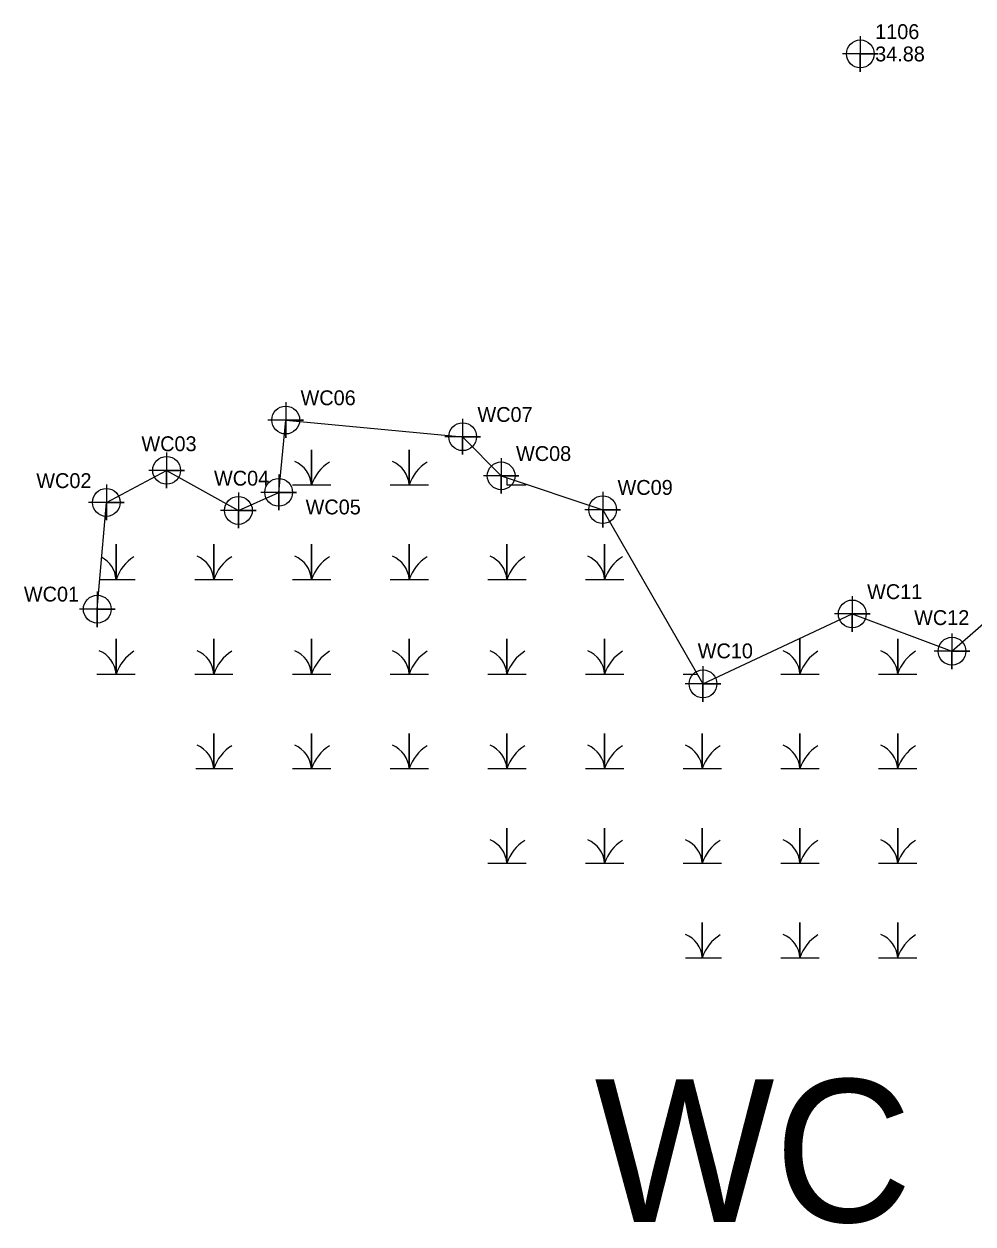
# Model space of a CAD drawing. Extents: x 2138832 to 2141061, y 149156 to 150675.
# Drawn here: x 2140241 to 2140400.8, y 149325.9 to 149527.9 of the extents above; entities that cross this region are included whole.
import ezdxf

# ---------------------------------------------------------------- set-up
doc = ezdxf.new("R2010")
doc.units = 0
for name, color, linetype in [('Default', 7, 'Continuous'), ('Exist Environmental Wetland Boundary', 7, 'Continuous'), ('Exist Environmental Wetland Boundary Cogo Number', 7, 'Continuous'), ('Exist Environmental Wetland Boundary Cogo Point CELL', 7, 'Continuous'), ('Exist Roads EOP Cogo Elevation', 7, 'Continuous'), ('Exist Roads EOP Cogo Number', 7, 'Continuous'), ('Exist Roads EOP Cogo Point CELL', 7, 'Continuous')]:
    doc.layers.add(name, color=color, linetype=linetype)

msp = doc.modelspace()

# ---------------------------------------------------------------- linework, layer by layer
at = {"layer": 'Exist Environmental Wetland Boundary'}
msp.add_lwpolyline([(2140253.29, 149429.4), (2140254.83, 149447.37), (2140264.97, 149452.77), (2140277.06, 149446.02), (2140283.85, 149449.07), (2140285.03, 149461.24), (2140314.82, 149458.43), (2140321.31, 149451.85), (2140338.41, 149446.15), (2140355.29, 149416.83), (2140380.43, 149428.6), (2140397.22, 149422.33), (2140417.64, 149440.18), (2140431.93, 149435.34), (2140440.91, 149448.03), (2140451.84, 149442.55), (2140443.59, 149426.19), (2140443.38, 149418.79), (2140459.22, 149412.06), (2140485.31, 149411.82), (2140462.13, 149440.8)], dxfattribs=at)
at = {"layer": 'Exist Environmental Wetland Boundary Cogo Point CELL'}
msp.add_line((2140351.96, 149418.48), (2140354.34, 149418.48), dxfattribs=at)
for points in [[(2140285.03, 149464.24), (2140285.03, 149458.24), (2140285.03, 149461.24), (2140288.03, 149461.24), (2140282.03, 149461.24)], [(2140314.82, 149461.43), (2140314.82, 149455.43), (2140314.82, 149458.43), (2140317.82, 149458.43), (2140311.82, 149458.43)], [(2140264.97, 149455.77), (2140264.97, 149449.77), (2140264.97, 149452.77), (2140267.97, 149452.77), (2140261.97, 149452.77)], [(2140286.15, 149450.32), (2140289.38, 149450.32), (2140289.38, 149456.24), (2140289.38, 149450.32), (2140292.6, 149450.32)], [(2140302.6, 149450.32), (2140305.83, 149450.32), (2140305.83, 149456.24), (2140305.83, 149450.32), (2140309.05, 149450.32)], [(2140321.31, 149454.85), (2140321.31, 149448.85), (2140321.31, 149451.85), (2140324.31, 149451.85), (2140318.31, 149451.85)], [(2140283.85, 149452.07), (2140283.85, 149446.07), (2140283.85, 149449.07), (2140286.85, 149449.07), (2140280.85, 149449.07)], [(2140254.83, 149450.37), (2140254.83, 149444.37), (2140254.83, 149447.37), (2140257.83, 149447.37), (2140251.83, 149447.37)], [(2140322.28, 149451.53), (2140322.28, 149450.32), (2140325.5, 149450.32)], [(2140277.06, 149449.02), (2140277.06, 149443.02), (2140277.06, 149446.02), (2140280.06, 149446.02), (2140274.06, 149446.02)], [(2140338.41, 149449.15), (2140338.41, 149443.15), (2140338.41, 149446.15), (2140341.41, 149446.15), (2140335.41, 149446.15)], [(2140253.72, 149434.4), (2140256.47, 149434.4), (2140256.47, 149440.32), (2140256.47, 149434.4), (2140259.7, 149434.4)], [(2140269.7, 149434.4), (2140272.93, 149434.4), (2140272.93, 149440.32), (2140272.93, 149434.4), (2140276.15, 149434.4)], [(2140286.15, 149434.4), (2140289.38, 149434.4), (2140289.38, 149440.32), (2140289.38, 149434.4), (2140292.6, 149434.4)], [(2140302.6, 149434.4), (2140305.83, 149434.4), (2140305.83, 149440.32), (2140305.83, 149434.4), (2140309.05, 149434.4)], [(2140319.05, 149434.4), (2140322.28, 149434.4), (2140322.28, 149440.32), (2140322.28, 149434.4), (2140325.5, 149434.4)], [(2140335.5, 149434.4), (2140338.73, 149434.4), (2140338.73, 149440.32), (2140338.73, 149434.4), (2140341.96, 149434.4)], [(2140253.29, 149432.4), (2140253.29, 149426.4), (2140253.29, 149429.4), (2140256.29, 149429.4), (2140250.29, 149429.4)], [(2140380.43, 149431.6), (2140380.43, 149425.6), (2140380.43, 149428.6), (2140383.43, 149428.6), (2140377.43, 149428.6)], [(2140253.25, 149418.48), (2140256.47, 149418.48), (2140256.47, 149424.4), (2140256.47, 149418.48), (2140259.7, 149418.48)], [(2140269.7, 149418.48), (2140272.93, 149418.48), (2140272.93, 149424.4), (2140272.93, 149418.48), (2140276.15, 149418.48)], [(2140286.15, 149418.48), (2140289.38, 149418.48), (2140289.38, 149424.4), (2140289.38, 149418.48), (2140292.6, 149418.48)], [(2140302.6, 149418.48), (2140305.83, 149418.48), (2140305.83, 149424.4), (2140305.83, 149418.48), (2140309.05, 149418.48)], [(2140319.05, 149418.48), (2140322.28, 149418.48), (2140322.28, 149424.4), (2140322.28, 149418.48), (2140325.5, 149418.48)], [(2140335.5, 149418.48), (2140338.73, 149418.48), (2140338.73, 149424.4), (2140338.73, 149418.48), (2140341.96, 149418.48)], [(2140368.41, 149418.48), (2140371.63, 149418.48), (2140371.63, 149424.4), (2140371.63, 149418.48), (2140374.86, 149418.48)], [(2140384.86, 149418.48), (2140388.08, 149418.48), (2140388.08, 149424.4), (2140388.08, 149418.48), (2140391.31, 149418.48)], [(2140397.22, 149425.33), (2140397.22, 149419.33), (2140397.22, 149422.33), (2140400.22, 149422.33), (2140394.22, 149422.33)], [(2140355.29, 149419.83), (2140355.29, 149413.83), (2140355.29, 149416.83), (2140358.29, 149416.83), (2140352.29, 149416.83)], [(2140269.91, 149402.56), (2140272.93, 149402.56), (2140272.93, 149408.48), (2140272.93, 149402.56), (2140276.15, 149402.56)], [(2140286.15, 149402.56), (2140289.38, 149402.56), (2140289.38, 149408.48), (2140289.38, 149402.56), (2140292.6, 149402.56)], [(2140302.6, 149402.56), (2140305.83, 149402.56), (2140305.83, 149408.48), (2140305.83, 149402.56), (2140309.05, 149402.56)], [(2140319.05, 149402.56), (2140322.28, 149402.56), (2140322.28, 149408.48), (2140322.28, 149402.56), (2140325.5, 149402.56)], [(2140335.5, 149402.56), (2140338.73, 149402.56), (2140338.73, 149408.48), (2140338.73, 149402.56), (2140341.96, 149402.56)], [(2140351.96, 149402.56), (2140355.18, 149402.56), (2140355.18, 149408.48), (2140355.18, 149402.56), (2140358.41, 149402.56)], [(2140368.41, 149402.56), (2140371.63, 149402.56), (2140371.63, 149408.48), (2140371.63, 149402.56), (2140374.86, 149402.56)], [(2140384.86, 149402.56), (2140388.08, 149402.56), (2140388.08, 149408.48), (2140388.08, 149402.56), (2140391.31, 149402.56)], [(2140319.05, 149386.65), (2140322.28, 149386.65), (2140322.28, 149392.56), (2140322.28, 149386.65), (2140325.5, 149386.65)], [(2140335.5, 149386.65), (2140338.73, 149386.65), (2140338.73, 149392.56), (2140338.73, 149386.65), (2140341.96, 149386.65)], [(2140351.96, 149386.65), (2140355.18, 149386.65), (2140355.18, 149392.56), (2140355.18, 149386.65), (2140358.41, 149386.65)], [(2140368.41, 149386.65), (2140371.63, 149386.65), (2140371.63, 149392.56), (2140371.63, 149386.65), (2140374.86, 149386.65)], [(2140384.86, 149386.65), (2140388.08, 149386.65), (2140388.08, 149392.56), (2140388.08, 149386.65), (2140391.31, 149386.65)], [(2140352.35, 149370.73), (2140355.18, 149370.73), (2140355.18, 149376.65), (2140355.18, 149370.73), (2140358.41, 149370.73)], [(2140368.41, 149370.73), (2140371.63, 149370.73), (2140371.63, 149376.65), (2140371.63, 149370.73), (2140374.86, 149370.73)], [(2140384.86, 149370.73), (2140388.08, 149370.73), (2140388.08, 149376.65), (2140388.08, 149370.73), (2140391.31, 149370.73)]]:
    msp.add_lwpolyline(points, dxfattribs=at)
for centre in [(2140285.03, 149461.24), (2140314.82, 149458.43), (2140264.97, 149452.77), (2140321.31, 149451.85), (2140254.83, 149447.37), (2140283.85, 149449.07), (2140277.06, 149446.02), (2140338.41, 149446.15), (2140253.29, 149429.4), (2140380.43, 149428.6), (2140397.22, 149422.33), (2140355.29, 149416.83)]:
    msp.add_circle(centre, 2.34, dxfattribs=at)
for centre, radius, start, end in [((2140284.78, 149449.99), 4.61, 4.1403, 67.535), ((2140296.22, 149448.05), 7.21, 122.1274, 161.6222), ((2140301.23, 149449.99), 4.61, 4.1403, 67.535), ((2140312.67, 149448.05), 7.21, 122.1274, 161.6222), ((2140251.87, 149434.07), 4.61, 4.1403, 61.9954), ((2140263.31, 149432.13), 7.21, 122.1274, 161.6222), ((2140268.33, 149434.07), 4.61, 4.1403, 67.535), ((2140279.77, 149432.13), 7.21, 122.1274, 161.6222), ((2140284.78, 149434.07), 4.61, 4.1403, 67.535), ((2140296.22, 149432.13), 7.21, 122.1274, 161.6222), ((2140301.23, 149434.07), 4.61, 4.1403, 67.535), ((2140312.67, 149432.13), 7.21, 122.1274, 161.6222), ((2140317.68, 149434.07), 4.61, 4.1403, 67.535), ((2140329.12, 149432.13), 7.21, 122.1274, 161.6222), ((2140334.13, 149434.07), 4.61, 4.1403, 67.535), ((2140345.57, 149432.13), 7.21, 122.1274, 161.6222), ((2140251.87, 149418.15), 4.61, 4.1403, 67.535), ((2140263.31, 149416.21), 7.21, 122.1274, 161.6222), ((2140268.33, 149418.15), 4.61, 4.1403, 67.535), ((2140279.77, 149416.21), 7.21, 122.1274, 161.6222), ((2140284.78, 149418.15), 4.61, 4.1403, 67.535), ((2140296.22, 149416.21), 7.21, 122.1274, 161.6222), ((2140301.23, 149418.15), 4.61, 4.1403, 67.535), ((2140312.67, 149416.21), 7.21, 122.1274, 161.6222), ((2140317.68, 149418.15), 4.61, 4.1403, 67.535), ((2140329.12, 149416.21), 7.21, 122.1274, 161.6222), ((2140334.13, 149418.15), 4.61, 4.1403, 67.535), ((2140345.57, 149416.21), 7.21, 122.1274, 161.6222), ((2140367.03, 149418.15), 4.61, 4.1403, 67.535), ((2140378.47, 149416.21), 7.21, 122.1274, 161.6222), ((2140383.48, 149418.15), 4.61, 4.1403, 67.535), ((2140394.92, 149416.21), 7.21, 122.1274, 161.6222), ((2140268.33, 149402.23), 4.61, 4.1403, 67.535), ((2140279.77, 149400.29), 7.21, 122.1274, 161.6222), ((2140284.78, 149402.23), 4.61, 4.1403, 67.535), ((2140296.22, 149400.29), 7.21, 122.1274, 161.6222), ((2140301.23, 149402.23), 4.61, 4.1403, 67.535), ((2140312.67, 149400.29), 7.21, 122.1274, 161.6222), ((2140317.68, 149402.23), 4.61, 4.1403, 67.535), ((2140329.12, 149400.29), 7.21, 122.1274, 161.6222), ((2140334.13, 149402.23), 4.61, 4.1403, 67.535), ((2140345.57, 149400.29), 7.21, 122.1274, 161.6222), ((2140350.58, 149402.23), 4.61, 4.1403, 67.535), ((2140362.02, 149400.29), 7.21, 122.1274, 161.6222), ((2140367.03, 149402.23), 4.61, 4.1403, 67.535), ((2140378.47, 149400.29), 7.21, 122.1274, 161.6222), ((2140383.48, 149402.23), 4.61, 4.1403, 67.535), ((2140394.92, 149400.29), 7.21, 122.1274, 161.6222), ((2140317.68, 149386.31), 4.61, 4.1403, 67.535), ((2140329.12, 149384.37), 7.21, 122.1274, 161.6222), ((2140334.13, 149386.31), 4.61, 4.1403, 67.535), ((2140345.57, 149384.37), 7.21, 122.1274, 161.6222), ((2140350.58, 149386.31), 4.61, 4.1403, 67.535), ((2140362.02, 149384.37), 7.21, 122.1274, 161.6222), ((2140367.03, 149386.31), 4.61, 4.1403, 67.535), ((2140378.47, 149384.37), 7.21, 122.1274, 161.6222), ((2140383.48, 149386.31), 4.61, 4.1403, 67.535), ((2140394.92, 149384.37), 7.21, 122.1274, 161.6222), ((2140350.58, 149370.4), 4.61, 4.1403, 67.535), ((2140362.02, 149368.46), 7.21, 122.1274, 161.6222), ((2140367.03, 149370.4), 4.61, 4.1403, 67.535), ((2140378.47, 149368.46), 7.21, 122.1274, 161.6222), ((2140383.48, 149370.4), 4.61, 4.1403, 67.535), ((2140394.92, 149368.46), 7.21, 122.1274, 161.6222)]:
    msp.add_arc(centre, radius, start, end, dxfattribs=at)
at = {"layer": 'Exist Roads EOP Cogo Point CELL'}
msp.add_lwpolyline([(2140381.79, 149525.88), (2140381.79, 149519.88), (2140381.79, 149522.88), (2140384.79, 149522.88), (2140378.79, 149522.88)], dxfattribs=at)
msp.add_circle((2140381.79, 149522.88), 2.34, dxfattribs=at)

# ---------------------------------------------------------------- texts
at = {"layer": 'Default'}
msp.add_text('WC', height=24, dxfattribs=at).set_placement((2140337.04, 149326.24))
at = {"layer": 'Exist Environmental Wetland Boundary Cogo Number'}
for s, p in [('WC06', (2140287.53, 149463.74)), ('WC07', (2140317.32, 149460.93)), ('WC03', (2140260.73, 149456)), ('WC08', (2140323.81, 149454.35)), ('WC02', (2140243.03, 149449.79)), ('WC04', (2140272.95, 149450.2)), ('WC09', (2140340.91, 149448.65)), ('WC05', (2140288.38, 149445.36)), ('WC11', (2140382.93, 149431.1)), ('WC01', (2140240.94, 149430.69)), ('WC12', (2140390.85, 149426.73)), ('WC10', (2140354.41, 149421.13))]:
    msp.add_text(s, height=2.5, dxfattribs=at).set_placement(p)
at = {"layer": 'Exist Roads EOP Cogo Elevation'}
msp.add_text('34.88', height=2.5, dxfattribs=at).set_placement((2140384.29, 149521.62))
at = {"layer": 'Exist Roads EOP Cogo Number'}
msp.add_text('1106', height=2.5, dxfattribs=at).set_placement((2140384.29, 149525.38))

doc.saveas('drawing.dxf')
